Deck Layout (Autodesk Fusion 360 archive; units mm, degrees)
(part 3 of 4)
sketch "Right Launch Alley Wall" plane through (0, 0, 0) normal (0, 0, 1) x axis (1, 0, 0)
  line L1 (465, 200) -> (0.189, 200)
  line L2 (465, 200) -> (475.0152, 200)
  line L3 (465, 400) -> (465, 200.5)
  line L4 (475.0152, 200.5) -> (475.0152, 405.3897)
  line L5 (475.0152, 200.5) -> (465, 200.5)
  line L6 (465, 535) -> (465, 427.4801)
  line L7 (448.6603, 535) -> (465, 535)
  line L8 (465.6699, 579.4615) -> (444.3301, 542.5)
  line L9 (475, 576.9615) -> (475, 423.4891)
  circle C1 centre (470.0076, 235) radius 2.25
  circle C2 centre (470.0076, 235) radius 4
  circle C3 centre (470.0076, 350) radius 4
  circle C4 centre (470.0076, 350) radius 2.25
  circle C5 centre (465, 412) radius 2.25
  arc A1 centre (465, 412) radius 12 clockwise from (475.0152, 405.3897) to (465, 400)
  circle C6 centre (465, 412) radius 9
  arc A2 centre (465, 412) radius 12 clockwise from (468, 423.619) to (471.8571, 421.8478)
  circle C7 centre (470, 435) radius 4
  circle C8 centre (470, 435) radius 1.9
  circle C9 centre (470, 574) radius 1.9
  circle C10 centre (470, 574) radius 4
  circle C11 centre (470, 505) radius 1.9
  circle C12 centre (470, 505) radius 4
  circle C13 centre (450, 541) radius 1.9
  circle C14 centre (450, 541) radius 4
  arc A3 centre (448.6603, 540) radius 5 clockwise from (448.6603, 535) to (444.3301, 542.5)
  arc A4 centre (470, 576.9615) radius 5 clockwise from (465.6699, 579.4615) to (475, 576.9615)
  arc A5 centre (469, 427.4919) radius 4 clockwise from (468, 423.619) to (465, 427.4919)
  arc A6 centre (473, 423.4891) radius 2 clockwise from (475, 423.4891) to (471.8571, 421.8478)
  point P2 (475.0152, 200)
  point P6 (475.0152, 200)
  point P3 (465, 200)
  point P7 (465, 200)
  point P13 (465, 412)
  point P14 (465, 412)
  point P21 (465, 412)
  point P39 (465, 427.4801)
  coincident P2 P6
  coincident P3 P7
  perpendicular L1 L3
  perpendicular L2 L4
  concentric C1 C2
  concentric C3 C4
  coincident P13 P14
  concentric A1 C6
  perpendicular L4 L5
  vertical L6
  perpendicular L6 L7
  vertical L9
  coincident P14 P21
  concentric C7 C8
  concentric C9 C10
  concentric C11 C12
  concentric C13 C14
  tangent L7 A3
  tangent L8 A3
  tangent L8 A4
  tangent L9 A4
  tangent A2 A5
  coincident A5 P39
  tangent A2 A6
  tangent L9 A6
  dimension "d456" diameter C1 = 4.5
  dimension "d457" diameter C2 = 8
  dimension "d458" diameter C4 = 4.5
  dimension "d459" diameter C3 = 8
  dimension "d461" diameter C5 = 4.5
  dimension "d469" diameter C6 = 18
  dimension "d481" radius A2 = 12
  dimension "d484" radius A3 = 5
  dimension "d485" radius A4 = 5
  dimension "d486" radius A5 = 4
  dimension "d487" radius A6 = 2
extrude "Extrude76" new body sketch "Right Launch Alley Wall" profile of L2 L3 L4 C2 C3 A1 along normal blind 25 bodies "Right Launch Runway"
extrude "Extrude77" add sketch "Right Launch Alley Wall" profile of C1 C2 C3 C4 along normal blind 4
fillet "Fillet24" radius 1
fillet "Fillet25" radius 2
extrude "Extrude78" new body sketch "Right Launch Alley Wall" profile of L6 L7 L8 L9 A2 C7 C10 C12 C14 A3 A4 A5 A6 along normal blind 25 bodies "Right Launch Runway Top"
extrude "Extrude79" add sketch "Right Launch Alley Wall" profile of C7 C8 C9 C10 C11 C12 C13 C14 along normal blind 4
fillet "Fillet26" radius 0.8
extrude "Extrude80" new body sketch "Bottom Runways" along normal blind 25 bodies "Left Middle Runway"
extrude "Extrude81" add sketch "Bottom Runways" along normal blind 4
fillet "Fillet27" radius 1.4
extrude "Extrude82" new body sketch "Bottom Runways" along normal blind 25 bodies "Left Upper Runway"
extrude "Extrude83" add sketch "Bottom Runways" along normal blind 4
fillet "Fillet29" radius 2
fillet "Fillet30" radius 4
fillet "Fillet31" radius 2
fillet "Fillet32" radius 2
combine "Combine5"
fillet "Fillet33" radius 2
extrude "Extrude84" new body sketch "Top Runways" profile of L19 L20 L21 L22 K1 C33 C36 C37 along normal blind 25 bodies "Top Left Curve"
extrude "Extrude85" add sketch "Top Runways" profile of C33 C34 C35 C36 C37 C38 along normal blind 4
fillet "Fillet34" radius 2
fillet "Fillet35" radius 2
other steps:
derived_base_feature "Derived Base Feature" bodies "Flipper_Straight"
base_feature "Base Feature" bodies "Flipper_Straight (1)"
named bodies: "Flipper_Straight", "Flipper_Straight (1)", "Left Loweer Deck Section", "Middle Lower Deck Section", "Right Lower Deck Section", "Z Reload Plunger", "Reload Ball Release Lower Washer", "Reload Ball Release Drive", "Reload Ball Release Solenoid Coupling", "Reload Ball Release Slide", "Reload Ball Release Slide Coupling", "Left Loweer Deck Section (1)", "Reload Solenoid", "Reload Load Coupling Bushing", "Reload Load Flipper", "Reload Load Coupling", "Reload Load Retaining Washer", "Reload Ball Release Slide (1)", "Reload Ball Release Washer", "Top Right Corner", "Outer Runway Right", "Outer Runway Left", "Right Launch Runway", "Right Launch Runway Top", "Left Middle Runway", "Left Upper Runway", "Top Left Curve"

design "Pinball Flipper Full bushing"
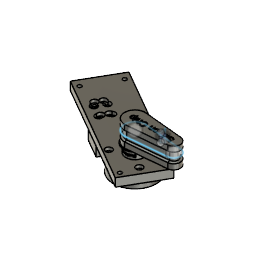
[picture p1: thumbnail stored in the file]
sketch "Flipper" plane through (0, 0, 0) normal (0, 0, 1) x axis (1, 0, 0)
  line L1 (47.7564, -7.9642) -> (0, -12.5)
  line L2 (47.766, 7.9632) -> (1.1968, 12.4426)
  line L3 (-3.0757, 6.1628) -> (6.875, 0.4178)
  line L4 (-6.875, -0.4178) -> (3.0757, -6.1628)
  arc A1 centre (0, 0) radius 12.5 clockwise from (2.3532, -12.2765) to (1.1968, 12.4426)
  arc A2 centre (47, 0) radius 8 clockwise from (47.766, 7.9632) to (47.7564, -7.9642)
  circle C1 centre (0, 0) radius 6.8
  circle C2 centre (3.7239, -2.15) radius 1.4
  circle C3 centre (-3.7239, 2.15) radius 1.4
  point P1 (0, 0)
  point P2 (0, 0)
  point P4 (0, -12.5)
  point P8 (2.3532, -12.2765)
  point P9 (0, 0)
  point P3 (47, 0)
  coincident P1 P2
  coincident P4 A1
  tangent L1 A2
  tangent L2 A1
  tangent L2 A2
  coincident L1 P8
  coincident P1 P9
  dimension "d6" diameter C1 = 13.6
  dimension "d87" angle P3 = 150
  dimension "d174" diameter P3 = 4
  dimension "d363" diameter C2 = 2.8
  dimension "d364" diameter C3 = 2.8
sketch "Bushing" plane through (0, 0, 0) normal (0, 0, 1) x axis (1, 0, 0)
  circle C1 centre (0, 0) radius 7.3
  circle C2 centre (0, 0) radius 11
  point P1 (0, 0)
  point P2 (0, 0)
  point P3 (0, 0)
  coincident P1 P2
  coincident P1 P3
extrude "Extrude1" new body sketch "Flipper" blind 25 from offset 0.7 bodies "DO NOT USE FLIPPER PROTO"
extrude "Extrude2" add sketch "Flipper" profile of C1 L4 L3 C2 C3 against normal blind 30.8 and along normal blind 0.7
sketch "Washers Upper" plane through (0, 0, 0) normal (0, 0, 1) x axis (1, 0, 0)
  circle C1 centre (0, 0) radius 13.5
  circle C2 centre (0, 0) radius 7.3
  point P1 (0, 0)
  point P2 (0, 0)
  point P3 (0, 0)
  coincident P1 P2
  coincident P1 P3
  dimension "d368" diameter C1 = 27
extrude "Extrude3" new body sketch "Washers Upper" blind -0.8 from offset 0.4 bodies "Washer Upper"
extrude "Extrude4" new body sketch "Bushing" blind -29 from offset -10.2 bodies "Base and Bushing"
sketch "Deck Section" plane through (0, 0, 0) normal (0, 0, 1) x axis (1, 0, 0)
  line L1 (-50, 50) -> (-50, 0)
  line L2 (50, 50) -> (-50, 50)
  line L3 (50, -50) -> (50, 50)
  line L4 (-50, -50) -> (50, -50)
  line L5 (-50, 0) -> (-50, -50)
  circle C1 centre (0, 0) radius 11.5
  point P1 (0, 0)
  point P2 (0, 0)
  coincident P1 P2
  vertical L1
  perpendicular L1 L2
  perpendicular L2 L3
  perpendicular L3 L4
  perpendicular L2 L5
extrude "Extrude5" new body sketch "Deck Section" blind -9 from offset -1.2 bodies "Base Section"
sketch "Solenoid Assembly" plane through (0, 0, -10.2) normal (0, 0, -1) x axis (1, 0, 0)
  line L1 (25, -25) -> (25, 25)
  line L2 (-100, -25) -> (25, -25)
  line L3 (-100, 25) -> (-100, -25)
  line L4 (25, 25) -> (-100, 25)
  circle C1 centre (0, 0) radius 11.5
  circle C2 centre (0, 0) radius 7.3
  point P1 (0, 0)
  point P3 (0, 0)
  coincident P1 P3
  vertical L1
  perpendicular L2 L3
  perpendicular L1 L4
sketch "Solenoid 22mm" plane through (0, 0, 0) normal (0, 0, 1) x axis (1, 0, 0)
  line L1 (-11, 0) -> (-11, -26)
  line L2 (11, -26) -> (11, 0)
  line L3 (-11, -26) -> (11, -26)
  line L4 (11, 0) -> (-11, 0)
  circle C1 centre (6, -5) radius 1.8
  circle C2 centre (-6, -20.5) radius 1.8
  point P2 (11, -26)
  point P3 (11, -26)
  point P4 (11, -26)
  coincident P2 P3
  horizontal L3
  perpendicular L1 L3
  perpendicular L1 L4
  coincident P2 P4
  perpendicular L2 L3
sketch "Solenoid 37mm" plane through (0, 0, 0) normal (0, 0, 1) x axis (1, 0, 0)
  line L1 (-2.5, -5.5015) -> (-2.506, -11.3658)
  line L2 (-11, 0) -> (-11, -37)
  line L3 (-5.5, -5.5015) -> (-5.494, -11.3656)
  line L4 (-11, 0) -> (11, 0)
  line L5 (2.5, -31.4995) -> (2.5022, -25.4191)
  line L6 (-2.5, -25.5008) -> (-2.503, -31.4046)
  line L7 (5.5, -25.5) -> (5.5, -31.5)
  line L8 (11, 0) -> (11, -37)
  line L9 (-5.5, -25.5) -> (-5.5, -31.5)
  line L10 (-11, -37) -> (11, -37)
  line L11 (2.5, -5.5015) -> (2.506, -11.3658)
  line L12 (-11, 0) -> (-11, -37)
  line L13 (-11, 0) -> (11, 0)
  line L14 (11, 0) -> (11, -37)
  line L15 (5.5, -5.5015) -> (5.494, -11.3656)
  line L16 (-11, -37) -> (11, -37)
  line L17 (-11, 0) -> (-11, -37)
  line L18 (-11, 0) -> (11, 0)
  line L19 (2.5, -31.4995) -> (2.5021, -25.5799)
  line L20 (5.5, -25.5) -> (5.5, -31.5)
  line L21 (11, 0) -> (11, -37)
  line L22 (-11, -37) -> (11, -37)
  circle C1 centre (4, -28.5) radius 1.5
  arc A1 centre (-4, -31.5) radius 1.5 clockwise from (-2.503, -31.4046) to (-5.5, -31.5)
  arc A2 centre (-4, -25.5) radius 1.5 clockwise from (-5.5, -25.5) to (-2.5, -25.5008)
  arc A3 centre (-4, -11.5) radius 1.5 clockwise from (-2.506, -11.3658) to (-5.494, -11.3656)
  arc A4 centre (4, -11.5) radius 1.5 clockwise from (5.4939, -11.365) to (2.5061, -11.365)
  circle C2 centre (-4, -28.5) radius 1.5
  arc A5 centre (4, -31.5) radius 1.5 clockwise from (5.5, -31.5) to (2.5, -31.4995)
  arc A6 centre (4, -25.5) radius 1.5 clockwise from (2.5022, -25.4191) to (5.5, -25.5)
  arc A7 centre (-4, -5.5) radius 1.5 clockwise from (-5.5, -5.5015) to (-2.5, -5.5015)
  circle C3 centre (-4, -8.5) radius 1.5
  circle C4 centre (4, -8.5) radius 1.5
  circle C5 centre (4, -28.5) radius 1.5
  arc A8 centre (-4, -31.5) radius 1.5 clockwise from (-2.503, -31.4045) to (-5.5, -31.5)
  arc A9 centre (4, -5.5) radius 1.5 clockwise from (2.5, -5.5015) to (5.5, -5.5015)
  arc A10 centre (-4, -11.5) radius 1.5 clockwise from (-2.5061, -11.365) to (-5.4939, -11.365)
  arc A11 centre (4, -11.5) radius 1.5 clockwise from (5.494, -11.3656) to (2.506, -11.3658)
  circle C6 centre (-4, -28.5) radius 1.5
  arc A12 centre (4, -31.5) radius 1.5 clockwise from (5.5, -31.5) to (2.5, -31.4995)
  circle C7 centre (-4, -8.5) radius 1.5
  circle C8 centre (4, -8.5) radius 1.5
  circle C9 centre (4, -28.5) radius 1.5
  arc A13 centre (-4, -31.5) radius 1.5 clockwise from (-2.503, -31.4045) to (-5.5, -31.5)
  arc A14 centre (-4, -11.5) radius 1.5 clockwise from (-2.5061, -11.365) to (-5.4939, -11.365)
  arc A15 centre (4, -11.5) radius 1.5 clockwise from (5.4939, -11.365) to (2.5061, -11.365)
  circle C10 centre (-4, -28.5) radius 1.5
  arc A16 centre (4, -31.5) radius 1.5 clockwise from (5.5, -31.5) to (2.5, -31.4995)
  arc A17 centre (4, -25.5) radius 1.5 clockwise from (2.5021, -25.5799) to (5.5, -25.5)
  circle C11 centre (-4, -8.5) radius 1.5
  circle C12 centre (4, -8.5) radius 1.5
  point P28 (2.5, -31.4995)
  point P7 (2.5, -31.4995)
  point P83 (2.5, -31.4995)
  point P67 (2.5, -31.4995)
  tangent L1 A7
  tangent L3 A7
  tangent A2 L6
  tangent A6 L7
  coincident P28 A5
  tangent A5 L5
  tangent A2 L9
  coincident P7 L5
  tangent A9 L15
  tangent L11 A9
  tangent A17 L20
  coincident P83 A16
  tangent A16 L19
  coincident P67 L19
extrude "Extrude6" new body sketch "Solenoid 22mm" along normal blind 25 bodies "Solenoid 22mm"
extrude "Extrude7" new body sketch "Solenoid 37mm" along normal blind 26 bodies "Solenoid 37mm"
sketch "Solenoid 37mm Plunger" plane through (0, -37, 0) normal (0, -1, 0) x axis (1, 0, 0)
  line L1 (11, 0) -> (-11, 0)
  line L2 (11, 26) -> (11, 0)
  line L3 (-11, 26) -> (11, 26)
  line L4 (-11, 0) -> (-11, 26)
  circle C1 centre (0, 12.5) radius 4
extrude "Extrude8" add sketch "Solenoid 37mm Plunger" profile of C1 along normal blind 23
sketch "Solenoid 22mm Plunger" plane through (0, -26, 0) normal (0, -1, 0) x axis (1, 0, 0)
  line L1 (11, 0) -> (-11, 0)
  line L2 (11, 25) -> (11, 0)
  line L3 (-11, 25) -> (11, 25)
  line L4 (-11, 0) -> (-11, 25)
  circle C1 centre (0, 12.5) radius 4
extrude "Extrude9" add sketch "Solenoid 22mm Plunger" profile of C1 along normal blind 20
sketch "Washer Lower TBA" plane through (0, 0, -10.2) normal (0, 0, -1) x axis (1, 0, 0)
  circle C1 centre (0, 0) radius 15
  circle C2 centre (0, 0) radius 11.5
  dimension "d38" diameter C1 = 30
move_face "MoveFace1"
extrude "Extrude11" cut sketch "Flipper" profile of C1 L4 L3 blind -19 taper 3 from offset -22.3
sketch "Flipper Drive" plane through (0, 0, -10.2) normal (0, 0, -1) x axis (1, 0, 0)
  line L1 (2.8887, 6.4858) -> (-7.0612, 0.7412)
  line L2 (7.0612, -0.7412) -> (-2.8887, -6.4858)
  line L3 (-7.5, 12.9904) -> (0, 0)
  line L4 (2.0367, 12.7229) -> (-5, 8.6603)
  line L5 (19.5843, 19.5843) -> (0, 0)
  line L6 (28.1764, 0) -> (0, 0)
  line L7 (-23.0757, -23.0757) -> (0, 0)
  line L8 (33.1997, 0) -> (0, 0)
  line L9 (5.1764, 19.3185) -> (0, 0)
  line L10 (26.3861, 0) -> (0, 0)
  line L11 (-5.1764, 19.3185) -> (0, 0)
  line L12 (28.3599, 0) -> (0, 0)
  line L13 (0, 0) -> (-5.1764, -19.3185)
  line L14 (0, 0) -> (5.1764, -19.3185)
  line L15 (19.1868, -19.1868) -> (0, 0)
  line L16 (27.1343, 0) -> (0, 0)
  line L17 (0, 0) -> (-19.1868, 19.1868)
  line L18 (23.3932, -6.2682) -> (0, 0)
  line L19 (24.2184, 0) -> (0, 0)
  line L20 (0, 0) -> (-22.295, 10.3963)
  line L21 (24.2161, 6.4887) -> (0, 0)
  line L22 (23.6444, 0) -> (0, 0)
  line L23 (0, 0) -> (-21.6626, -10.1014)
  line L24 (-28.4442, -13.2638) -> (0, 0)
  line L25 (31.3847, 0) -> (0, 0)
  line L26 (-25.8113, 12.036) -> (0, 0)
  line L27 (28.4796, 0) -> (0, 0)
  line L28 (29.5346, -7.9138) -> (23.3932, -6.2682)
  line L29 (31.5373, 8.4504) -> (24.2161, 6.4887)
  arc A1 centre (0, 0) radius 7.1 clockwise from (-2.8887, -6.4858) to (-7.0612, 0.7412)
  arc A2 centre (0, 0) radius 7.1 clockwise from (2.8887, 6.4858) to (7.0612, -0.7412)
  circle C1 centre (0, 0) radius 15
  arc A3 centre (0, 0) radius 7.1 clockwise from (-7.0612, 0.7412) to (2.8887, 6.4858)
  arc A4 centre (0, 0) radius 7.1 clockwise from (7.0612, -0.7412) to (-2.8887, -6.4858)
  arc A5 centre (0, 0) radius 20 clockwise from (-5.1764, 19.3185) to (5.1764, 19.3185)
  arc A6 centre (0, 0) radius 20 clockwise from (5.1764, -19.3185) to (-5.1764, -19.3185)
  arc A7 centre (0, 0) radius 16 clockwise from (11.3137, 11.3137) to (15.4548, 4.1411)
  arc A8 centre (0, 0) radius 16 clockwise from (15.4548, -4.1411) to (11.3137, -11.3137)
  arc A9 centre (0, 0) radius 16 clockwise from (-11.3137, -11.3137) to (-14.5009, -6.7619)
  arc A10 centre (0, 0) radius 16 clockwise from (-14.5009, 6.7619) to (-11.3137, 11.3137)
  arc A11 centre (0, 0) radius 16 clockwise from (15.4548, 4.1411) to (15.4548, -4.1411)
  arc A12 centre (0, 0) radius 16 clockwise from (-14.5009, -6.7619) to (-14.5009, 6.7619)
  arc A13 centre (0, 0) radius 21 clockwise from (-19.0325, -8.875) to (-19.0325, 8.875)
  arc A14 centre (0, 0) radius 26 clockwise from (18.3848, 18.3848) to (18.3848, -18.3848)
  arc A15 centre (0, 0) radius 26 clockwise from (-18.3848, -18.3848) to (-23.564, -10.9881)
  arc A16 centre (0, 0) radius 26 clockwise from (-23.564, 10.9881) to (-18.3848, 18.3848)
  arc A17 centre (0, 0) radius 26 clockwise from (18.3848, -18.3848) to (-18.3848, -18.3848)
  arc A18 centre (0, 0) radius 21 clockwise from (-14.8492, 14.8492) to (14.8492, 14.8492)
  arc A19 centre (0, 0) radius 26 clockwise from (-18.3848, 18.3848) to (18.3848, 18.3848)
  arc A20 centre (0, 0) radius 21 clockwise from (14.8492, -14.8492) to (-14.8492, -14.8492)
  circle C2 centre (-18.564, -12.9881) radius 1.75
  circle C3 centre (-18.564, -12.9881) radius 4
  circle C4 centre (-18.564, 13.0119) radius 1.75
  circle C5 centre (-18.564, 13.0119) radius 4
  circle C6 centre (18.436, 13.0119) radius 1.75
  circle C7 centre (18.436, 13.0119) radius 4
  circle C8 centre (18.436, -12.9881) radius 1.75
  circle C9 centre (18.436, -12.9881) radius 4
  arc A21 centre (0, 0) radius 26 clockwise from (-23.564, -10.9881) to (-23.564, 10.9881)
  point P1 (0, 0)
  point P2 (0, 0)
  point P3 (7.0612, -0.7412)
  point P8 (0, 0)
  point P12 (-7.5, 12.9904)
  point P7 (0, 0)
  point P15 (0, 0)
  point P14 (0, 0)
  point P18 (0, 0)
  point P11 (0, 0)
  point P21 (0, 0)
  point P23 (0, 0)
  point P26 (0, 0)
  point P27 (0, 0)
  point P30 (0, 0)
  point P33 (0, 0)
  point P38 (0, 0)
  point P43 (0, 0)
  point P49 (15.4548, 4.1411)
  point P50 (11.3137, 11.3137)
  point P48 (0, 0)
  point P53 (15.4548, -4.1411)
  point P36 (0, 0)
  point P51 (0, 0)
  point P55 (-14.5009, -6.7619)
  point P54 (0, 0)
  point P57 (-19.0325, -8.875)
  point P58 (-19.0325, 8.875)
  point P61 (-14.5009, 6.7619)
  point P60 (-11.3137, 11.3137)
  point P59 (0, 0)
  point P62 (0, 0)
  point P46 (-21.6626, -10.1014)
  point P65 (0, 0)
  point P41 (-22.295, 10.3963)
  point P68 (0, 0)
  point P13 (0, 0)
  point P71 (0, 0)
  point P75 (18.3848, 18.3848)
  point P77 (-23.564, -10.9881)
  point P76 (0, 0)
  point P81 (-23.564, 10.9881)
  point P79 (0, 0)
  point P82 (0, 0)
  point P85 (-14.8492, 14.8492)
  point P83 (0, 0)
  point P86 (0, 0)
  point P88 (-14.8492, -14.8492)
  point P73 (0, 0)
  point P87 (0, 0)
  point P42 (0, 0)
  point P98 (0, 0)
  coincident P1 P2
  coincident P3 A1
  coincident P2 P8
  concentric A1 C1
  coincident C1 P12
  horizontal L6
  coincident P7 P15
  horizontal L8
  coincident P14 P18
  horizontal L10
  coincident P11 P21
  horizontal L12
  coincident P2 P23
  coincident P26 P27
  coincident P27 P30
  horizontal L16
  coincident P7 P33
  horizontal L19
  coincident P11 P38
  horizontal L22
  coincident P2 P43
  coincident L21 P49
  coincident L5 P50
  coincident P14 P48
  coincident L18 P53
  coincident P36 P51
  coincident L23 P55
  coincident P1 P54
  coincident L23 P57
  coincident L20 P58
  coincident L20 P61
  coincident L17 P60
  coincident P27 P59
  horizontal L25
  coincident P1 P62
  coincident P46 L24
  parallel L23 L24
  horizontal L27
  coincident P7 P65
  coincident P41 L26
  parallel L20 L26
  coincident P51 P68
  parallel L18 L28
  parallel L21 L29
  coincident P13 P71
  coincident L5 P75
  coincident L24 P77
  coincident P13 P76
  coincident L26 P81
  coincident P54 P79
  coincident P54 P82
  coincident L17 P85
  coincident P82 P83
  coincident P59 P86
  coincident L7 P88
  coincident P73 P87
  concentric C2 C3
  concentric C4 C5
  concentric C8 C9
  concentric C6 C7
  coincident P42 P98
  dimension "d299" angle L7 L8 = 135
  dimension "d300" angle L9 L10 = 75
  dimension "d301" angle L11 L12 = 105
  dimension "d302" radius A5 = 20
  dimension "d303" radius A6 = 20
  dimension "d307" radius A7 = 16
  dimension "d309" radius A8 = 16
  dimension "d311" radius A9 = 16
  dimension "d314" radius A10 = 16
  dimension "d513" radius A14 = 26
  dimension "d514" radius A15 = 26
  dimension "d515" radius A16 = 26
  dimension "d517" radius A18 = 21
  dimension "d518" radius A20 = 21
  dimension "d520" diameter C2 = 3.5
  dimension "d521" diameter C3 = 8
  dimension "d522" diameter C4 = 3.5
  dimension "d523" diameter C5 = 8
  dimension "d524" diameter C8 = 3.5
  dimension "d525" diameter C9 = 8
  dimension "d526" diameter C6 = 3.5
  dimension "d527" diameter C7 = 8
work_plane "WorkPlane1" RotateAngle 90
sketch "Flipper Drive Perpendicular Plane" plane through (0, 0, 0) normal (-0.866, 0.5, 0) x axis (-0.5, -0.866, 0)
  circle C1 centre (10, -32.2) radius 2
  circle C2 centre (10, -32.2) radius 4.5
  circle C3 centre (-10, -32.2) radius 2
  circle C4 centre (-10, -32.2) radius 4.5
  dimension "d51" diameter C1 = 4
  dimension "d52" diameter C2 = 9
  dimension "d53" diameter C3 = 4
  dimension "d54" diameter C4 = 9
extrude "Extrude12" new body sketch "Flipper Drive" profile of A2 C1 A3 A4 blind 8.8 from offset 11.2 bodies "Flipper Drive"
extrude "Extrude13" add sketch "Flipper Drive" profile of L1 L2 L3 A3 A4 blind 8.8 taper 3 from offset 11.2
sketch "Flipper Drive Top Labelling" plane through (0, 0, -30.2) normal (0, 0, -1) x axis (1, 0, 0)
  line L1 (3.3862, 6.2405) -> (-7.0975, 0.1877)
  line L2 (-3.3862, -6.2405) -> (7.0975, -0.1877)
  curve K1
  curve K2
  curve K3
  curve K4
  curve K5
  curve K6
  curve K7
  curve K8
  line L3 (10, 0) -> (0, 0)
  line L4 (3.3862, 6.2405) -> (-7.0975, 0.1877)
  line L5 (-3.3862, -6.2405) -> (7.0975, -0.1877)
  arc A1 centre (0, 0) radius 7.1 clockwise from (-3.3862, -6.2405) to (-7.0975, 0.1877)
  circle C1 centre (-5, 8.6603) radius 5
  circle C2 centre (-5, 8.6603) radius 3
  circle C3 centre (-5, 8.6603) radius 1.4
  arc A2 centre (0, 0) radius 7.1 clockwise from (3.3862, 6.2405) to (7.0975, -0.1877)
  circle C4 centre (0, 0) radius 15
  arc A3 centre (0, 0) radius 7.1 clockwise from (-3.3862, -6.2405) to (-7.0975, 0.1877)
  arc A4 centre (0, 0) radius 7.1 clockwise from (3.3862, 6.2405) to (7.0975, -0.1877)
  circle C5 centre (0, 0) radius 15
  point P1 (0, 0)
  point P8 (0, 0)
  horizontal L3
  coincident P1 P8
  concentric C1 C2
  concentric C1 C3
  dimension "d512" diameter C3 = 2.8
  dimension "d75" Text1-Height = 5
  dimension "d77" Text2-Height = 3
extrude "Extrude20" cut sketch "Flipper Drive Top Labelling" against normal blind 0.6
sketch "Flipper Drive Lower Assembly" plane through (0, 0, -10.2) normal (0, 0, -1) x axis (1, 0, 0)
  line L1 (40.6874, -6.549) -> (14.7287, 38.4892)
  line L2 (-113.7703, -35.5739) -> (14.7287, 38.4892)
  line L3 (-87.8117, -80.6121) -> (12.9793, -22.5191)
  line L4 (40.6874, -6.549) -> (12.9793, -22.5191)
  line L5 (-87.8117, -80.6121) -> (-113.7703, -35.5739)
  line L6 (20.7934, 41.9847) -> (14.7287, 38.4892)
  line L7 (46.7521, -3.0534) -> (40.6874, -6.549)
  line L8 (-94.1551, -30.9647) -> (-102.8153, -35.9647)
  line L9 (-83.4756, -35.9647) -> (-102.8153, -35.9647)
  line L10 (-90.691, -28.9647) -> (-94.1551, -30.9647)
  line L11 (19.0606, 40.986) -> (14.7287, 38.4892)
  circle C1 centre (0, 0) radius 11
  circle C2 centre (-82.8153, -70.6057) radius 2.25
  circle C3 centre (-102.8153, -35.9647) radius 2.25
  circle C4 centre (12.3745, 30.5207) radius 2.25
  circle C5 centre (32.3745, -4.1204) radius 2.25
  point P1 (0, 0)
  point P2 (0, 0)
  point P9 (-102.8153, -35.9647)
  point P14 (-102.8153, -35.9647)
  point P15 (-94.1551, -30.9647)
  point P17 (-90.691, -28.9647)
  point P3 (14.7287, 38.4892)
  point P18 (19.0606, 40.986)
  coincident P1 P2
  perpendicular L1 L2
  perpendicular L1 L4
  perpendicular L3 L5
  perpendicular L1 L6
  perpendicular L1 L7
  horizontal L9
  coincident P9 P14
  parallel L8 L10
  perpendicular L1 L11
  dimension "d132" diameter C2 = 4.5
  dimension "d135" diameter C3 = 4.5
  dimension "d138" diameter C4 = 4.5
  dimension "d139" diameter C5 = 4.5
  dimension "d348" angle L8 L9 = 30
  dimension "d349" distance P14 P15 = 10
  dimension "d357" distance P15 P17 = 4
  dimension "d534" distance P3 P18 = 5
extrude "Extrude21" add sketch "Flipper Drive Lower Assembly" profile of C1 L1 L2 L3 L4 L5 along normal blind 10
sketch "Washer Lower" plane through (0, 0, -20.2) normal (0, 0, -1) x axis (1, 0, 0)
  circle C1 centre (0, 0) radius 7.3
  circle C2 centre (0, 0) radius 7.3
  circle C3 centre (0, 0) radius 13.5
  point P1 (0, 0)
  point P3 (0, 0)
  coincident P1 P3
  dimension "d369" diameter C3 = 27
extrude "Extrude22" new body sketch "Washer Lower" blind 1 from offset 0.2 bodies "Washer Lower"
move "Move1"
move "Move2"
move "Move3"
move "Move4"
work_plane "WorkPlane2" RotateAngle 0
sketch "Construction to Solenoid" plane through (0, 0, -32.2) normal (0, 0, 1) x axis (1, 0, 0)
  line L1 (-83.5481, 36.6895) -> (-5, -8.6603)
  line L2 (85.6995, -8.6603) -> (-5, -8.6603)
  point P2 (-5, -8.6603)
  point P3 (-5, -8.6603)
  horizontal L2
  coincident P2 P3
  dimension "d87" angle L1 L2 = 150
move "Move5"
work_axis "WorkAxis2"
move "Move6"
move "Move7"
work_plane "WorkPlane3" AlongDistance 12.5
work_plane "WorkPlane4" RotateAngle 0
work_plane "WorkPlane5" RotateAngle 0
sketch "Solenoid Coupling" plane through (0, 0, -32.2) normal (0, 0, 1) x axis (1, 0, 0)
  line L1 (14.8548, -15.2705) -> (9.7533, -24.1063)
  line L2 (30.5284, -24.3335) -> (14.8548, -15.2705)
  line L3 (25.433, -33.159) -> (30.5284, -24.3335)
  line L4 (25.433, -33.159) -> (9.7533, -24.1063)
  line L5 (47.3229, -34.0286) -> (34.864, -26.8366)
  line L6 (30.5284, -24.3335) -> (34.864, -26.8366)
  line L7 (34.864, -26.8366) -> (30.629, -34.173)
  line L8 (13.6506, -26.3564) -> (16.6506, -21.1603)
  line L9 (22.6506, -21.1603) -> (16.6506, -21.1603)
  line L10 (13.6506, -26.3564) -> (16.6506, -21.1603)
  line L11 (51.0602, -47.9614) -> (53.55, -46.5429)
  line L12 (51.0602, -47.9614) -> (42.896, -43.2346)
  line L13 (-25.136, -26.8366) -> (-29.3244, -34.0923)
  line L14 (-45.1452, -15.2705) -> (-50.2467, -24.1063)
  line L15 (-34.567, -33.159) -> (-29.4716, -24.3335)
  line L16 (-46.3494, -26.3564) -> (-43.3494, -21.1603)
  line L17 (-8.2143, -48.5931) -> (-5.4963, -46.9921)
  line L18 (-11.811, -34.5286) -> (-25.136, -26.8366)
  line L19 (-29.4716, -24.3335) -> (-25.136, -26.8366)
  line L20 (-29.4716, -24.3335) -> (-45.1452, -15.2705)
  line L21 (-37.3494, -21.1603) -> (-43.3494, -21.1603)
  line L22 (-46.3494, -26.3564) -> (-43.3494, -21.1603)
  line L23 (-10.945, -35.0285) -> (-11.811, -34.5286)
  line L24 (-15.3719, -42.1478) -> (-16.2379, -41.6478)
  line L25 (-89.4716, -24.3335) -> (-105.1452, -15.2705)
  line L26 (-97.3494, -21.1603) -> (-103.3494, -21.1603)
  line L27 (-67.4648, -48.7967) -> (-64.8096, -47.2494)
  line L28 (-106.3494, -26.3564) -> (-103.3494, -21.1603)
  line L29 (-106.3494, -26.3564) -> (-103.3494, -21.1603)
  line L30 (-69.7504, -35.7181) -> (-70.6165, -35.2181)
  line L31 (-70.6165, -35.2181) -> (-85.136, -26.8366)
  line L32 (-74.5059, -42.6477) -> (-75.3719, -42.1477)
  line L33 (-85.136, -26.8366) -> (-89.3244, -34.0922)
  line L34 (-67.4648, -48.7967) -> (-75.3719, -44.2345)
  line L35 (-89.4716, -24.3335) -> (-85.136, -26.8366)
  line L36 (-94.567, -33.159) -> (-89.4716, -24.3335)
  line L37 (-105.1452, -15.2705) -> (-110.2467, -24.1063)
  line L38 (-94.567, -33.159) -> (-110.2467, -24.1063)
  line L39 (-156.3494, -26.3564) -> (-153.3494, -21.1603)
  line L40 (-155.1452, -15.2705) -> (-160.2467, -24.1063)
  line L41 (-147.3494, -21.1603) -> (-153.3494, -21.1603)
  line L42 (-119.2129, -36.0285) -> (-120.0789, -35.5285)
  line L43 (-116.307, -49.4732) -> (-113.7939, -48.0094)
  line L44 (-156.3494, -26.3564) -> (-153.3494, -21.1603)
  line L45 (-144.567, -33.159) -> (-139.4716, -24.3335)
  line L46 (-134.27, -27.3366) -> (-138.4584, -34.5922)
  line L47 (-144.567, -33.159) -> (-160.2467, -24.1063)
  line L48 (-139.4716, -24.3335) -> (-134.27, -27.3366)
  line L49 (-139.4716, -24.3335) -> (-155.1452, -15.2705)
  line L50 (-120.0789, -35.5285) -> (-134.27, -27.3366)
  line L51 (-123.6398, -43.1477) -> (-124.5059, -42.6477)
  line L52 (-116.307, -49.4732) -> (-124.5058, -44.7345)
  line L53 (-204.567, -33.159) -> (-220.2467, -24.1063)
  line L54 (-182.7738, -43.6477) -> (-183.6398, -43.1477)
  line L55 (-207.3494, -21.1603) -> (-213.3494, -21.1603)
  line L56 (-215.1452, -15.2705) -> (-220.2467, -24.1063)
  line L57 (-216.3494, -26.3564) -> (-213.3494, -21.1603)
  line L58 (-216.3494, -26.3564) -> (-213.3494, -21.1603)
  line L59 (-199.4716, -24.3335) -> (-215.1452, -15.2705)
  line L60 (-199.4716, -24.3335) -> (-193.404, -27.8366)
  line L61 (-178.3469, -36.5285) -> (-179.2129, -36.0285)
  line L62 (-179.2129, -36.0285) -> (-193.404, -27.8366)
  line L63 (-175.4401, -49.9688) -> (-183.6398, -45.2345)
  line L64 (-204.567, -33.159) -> (-199.4716, -24.3335)
  line L65 (-175.4401, -49.9688) -> (-172.9348, -48.5134)
  line L66 (-193.404, -27.8366) -> (-197.5924, -35.0922)
  line L67 (-264.567, -33.159) -> (-280.2467, -24.1063)
  line L68 (-275.1452, -15.2705) -> (-280.2467, -24.1063)
  line L69 (-234.5746, -50.467) -> (-232.0726, -49.0156)
  line L70 (-238.3469, -36.5285) -> (-252.538, -28.3366)
  line L71 (-259.4716, -24.3335) -> (-252.538, -28.3366)
  line L72 (-252.538, -28.3366) -> (-256.7263, -35.5922)
  line L73 (-234.5746, -50.467) -> (-242.7738, -45.7345)
  line L74 (-259.4716, -24.3335) -> (-275.1452, -15.2705)
  line L75 (-267.3494, -21.1603) -> (-273.3494, -21.1603)
  line L76 (-276.3494, -26.3564) -> (-273.3494, -21.1603)
  line L77 (-276.3494, -26.3564) -> (-273.3494, -21.1603)
  line L78 (-264.567, -33.159) -> (-259.4716, -24.3335)
  line L79 (25.433, -33.159) -> (42.896, -43.2346)
  line L80 (30.629, -34.173) -> (29.7699, -35.6612)
  line L81 (-30.2298, -35.6615) -> (-29.3244, -34.0923)
  line L82 (-90.23, -35.6618) -> (-75.3719, -44.2345)
  line L83 (-90.23, -35.6618) -> (-89.3244, -34.0922)
  line L84 (-90.23, -35.6618) -> (-94.567, -33.159)
  line L85 (-144.567, -33.159) -> (-124.5058, -44.7345)
  line L86 (-139.3638, -36.1613) -> (-138.4584, -34.5922)
  line L87 (-204.567, -33.159) -> (-183.6398, -45.2345)
  line L88 (-198.4977, -36.6611) -> (-197.5924, -35.0922)
  line L89 (-264.567, -33.159) -> (-242.7738, -45.7345)
  line L90 (-257.6316, -37.161) -> (-256.7263, -35.5922)
  line L91 (-326.2039, -23.3339) -> (-319.2703, -27.337)
  line L92 (-331.2993, -32.1594) -> (-346.979, -23.1067)
  line L93 (-343.0816, -25.3568) -> (-340.0816, -20.1607)
  line L94 (-299.5746, -50.467) -> (-297.0726, -49.0156)
  line L95 (-343.0816, -25.3568) -> (-340.0816, -20.1607)
  line L96 (-334.0816, -20.1607) -> (-340.0816, -20.1607)
  line L97 (-326.2039, -23.3339) -> (-341.8775, -14.2709)
  line L98 (-303.3473, -36.5287) -> (-319.2703, -27.337)
  line L99 (-331.2993, -32.1594) -> (-326.2039, -23.3339)
  line L100 (-319.2703, -27.337) -> (-323.4586, -34.5926)
  line L101 (-299.5746, -50.467) -> (-307.7738, -45.7345)
  line L102 (-331.2993, -32.1594) -> (-307.7738, -45.7345)
  line L103 (-341.8775, -14.2709) -> (-346.979, -23.1067)
  line L104 (-324.3639, -36.1614) -> (-323.4586, -34.5926)
  line L105 (-326.0961, -35.1618) -> (-324.3639, -36.1614)
  line L106 (-393.0316, -31.1598) -> (-367.7738, -45.7345)
  line L107 (-381.0025, -26.3374) -> (-385.1909, -33.593)
  line L108 (-386.0961, -35.1618) -> (-385.1909, -33.593)
  line L109 (-393.0316, -31.1598) -> (-408.7112, -22.1071)
  line L110 (-403.6098, -13.2713) -> (-408.7112, -22.1071)
  line L111 (-387.9362, -22.3343) -> (-403.6098, -13.2713)
  line L112 (-395.8139, -19.1611) -> (-401.8139, -19.1611)
  line L113 (-387.9362, -22.3343) -> (-381.0025, -26.3374)
  line L114 (-393.0316, -31.1598) -> (-387.9362, -22.3343)
  line L115 (-359.5746, -50.467) -> (-367.7738, -45.7345)
  line L116 (-404.8139, -24.3572) -> (-401.8139, -19.1611)
  line L117 (-363.3476, -36.5288) -> (-381.0025, -26.3374)
  line L118 (-404.8139, -24.3572) -> (-401.8139, -19.1611)
  line L119 (-359.5746, -50.467) -> (-357.0726, -49.0156)
  line L120 (-387.8284, -34.1622) -> (-386.0961, -35.1618)
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  point P3 (16.6506, -21.1603)
  point P13 (16.6506, -21.1603)
  point P16 (13.6506, -26.3564)
  point P22 (-43.3494, -21.1603)
  point P33 (-43.3494, -21.1603)
  point P35 (-46.3494, -26.3564)
  point P48 (-103.3494, -21.1603)
  point P55 (-103.3494, -21.1603)
  point P47 (-106.3494, -26.3564)
  point P67 (-153.3494, -21.1603)
  point P78 (-153.3494, -21.1603)
  point P65 (-156.3494, -26.3564)
  point P92 (-213.3494, -21.1603)
  point P94 (-213.3494, -21.1603)
  point P93 (-216.3494, -26.3564)
  point P111 (-273.3494, -21.1603)
  point P115 (-273.3494, -21.1603)
  point P112 (-276.3494, -26.3564)
  point P127 (29.7699, -35.6612)
  point P130 (-139.3638, -36.1613)
  point P131 (-198.4977, -36.6611)
  point P132 (-257.6316, -37.161)
  point P138 (-340.0816, -20.1607)
  point P139 (-340.0816, -20.1607)
  point P136 (-343.0816, -25.3568)
  point P133 (-324.3639, -36.1614)
  point P155 (-401.8139, -19.1611)
  point P161 (-401.8139, -19.1611)
  point P159 (-404.8139, -24.3572)
  point P158 (-386.0961, -35.1618)
  point P14 (13.6506, -26.3564)
  point P34 (-46.3494, -26.3564)
  point P30 (-11.811, -34.5286)
  point P40 (-10.945, -35.0285)
  point P28 (-16.2379, -41.6478)
  point P41 (-15.3719, -42.1478)
  point P46 (-106.3494, -26.3564)
  point P49 (-69.7504, -35.7181)
  point P61 (-70.6165, -35.2181)
  point P51 (-74.5059, -42.6477)
  point P54 (-75.3719, -42.1477)
  point P74 (-156.3494, -26.3564)
  point P72 (-119.2129, -36.0285)
  point P83 (-120.0789, -35.5285)
  point P75 (-123.6398, -43.1477)
  point P77 (-124.5059, -42.6477)
  point P98 (-216.3494, -26.3564)
  point P91 (-178.3469, -36.5285)
  point P105 (-179.2129, -36.0285)
  point P99 (-182.7738, -43.6477)
  point P101 (-183.6398, -43.1477)
  point P124 (-276.3494, -26.3564)
  point P146 (-343.0816, -25.3568)
  point P153 (-326.0961, -35.1618)
  point P167 (-404.8139, -24.3572)
  point P154 (-387.8284, -34.1622)
  perpendicular L3 L4
  perpendicular L3 L6
  perpendicular L5 L7
  horizontal L9
  coincident P3 P13
  perpendicular L4 L8
  coincident L8 P16
  coincident L4 P16
  perpendicular L15 L19
  perpendicular L13 L18
  horizontal L21
  coincident P22 P33
  coincident P35 L22
  parallel L18 L23
  perpendicular L36 L38
  perpendicular L35 L36
  perpendicular L31 L33
  horizontal L26
  coincident P48 P55
  perpendicular L28 L38
  coincident P47 L28
  coincident P47 L38
  parallel L30 L31
  perpendicular L45 L47
  perpendicular L45 L48
  perpendicular L46 L50
  horizontal L41
  coincident P67 P78
  perpendicular L39 L47
  coincident P65 L39
  coincident P65 L47
  parallel L42 L50
  perpendicular L53 L64
  perpendicular L60 L64
  perpendicular L62 L66
  horizontal L55
  coincident P92 P94
  perpendicular L53 L57
  coincident P93 L57
  coincident P93 L53
  parallel L61 L62
  perpendicular L67 L78
  perpendicular L71 L78
  perpendicular L70 L72
  horizontal L75
  coincident P111 P115
  perpendicular L67 L77
  coincident P112 L77
  coincident P112 L67
  coincident L79 P127
  parallel L7 L80
  parallel L34 L82
  perpendicular L82 L83
  coincident L85 P130
  perpendicular L85 L86
  coincident L87 P131
  perpendicular L87 L88
  coincident L89 P132
  perpendicular L89 L90
  perpendicular L92 L99
  perpendicular L91 L99
  perpendicular L98 L100
  horizontal L96
  coincident P138 P139
  perpendicular L92 L93
  coincident P136 L93
  coincident P136 L92
  coincident P133 L102
  perpendicular L102 L104
  perpendicular L104 L105
  perpendicular L109 L114
  perpendicular L113 L114
  perpendicular L107 L117
  horizontal L112
  coincident P155 P161
  perpendicular L109 L118
  coincident P159 L118
  coincident P159 L109
  coincident P158 L106
  perpendicular L106 L108
  perpendicular L108 L120
  dimension "d206" diameter = 6.5
  dimension "d232" angle L8 L9 = 120
  dimension "d233" distance P13 P14 = 6
  dimension "d237" diameter = 6.5
  dimension "d238" angle L21 L22 = 120
  dimension "d239" distance P33 P34 = 6
  dimension "d240" distance P30 P40 = 1
  dimension "d241" distance P28 P41 = 1
  dimension "d242" diameter = 6.5
  dimension "d243" angle L26 L28 = 120
  dimension "d244" distance P46 P48 = 6
  dimension "d245" distance P49 P61 = 1
  dimension "d246" distance P51 P54 = 1
  dimension "d247" diameter = 6.5
  dimension "d248" angle L39 L41 = 120
  dimension "d249" distance P67 P74 = 6
  dimension "d250" distance P72 P83 = 1
  dimension "d251" distance P75 P77 = 1
  dimension "d252" diameter = 6.5
  dimension "d253" angle L55 L57 = 120
  dimension "d254" distance P94 P98 = 6
  dimension "d255" distance P91 P105 = 1
  dimension "d256" distance P99 P101 = 1
  dimension "d257" diameter = 6.5
  dimension "d258" angle L75 L77 = 120
  dimension "d259" distance P115 P124 = 6
  dimension "d350" radius = 7
  dimension "d351" radius = 7
  dimension "d352" radius = 6.7
  dimension "d353" radius = 7
  dimension "d354" radius = 7
  dimension "d355" radius = 7
  dimension "d421" diameter = 6.5
  dimension "d422" angle L93 L96 = 120
  dimension "d423" distance P139 P146 = 6
  dimension "d424" radius = 7
  dimension "d425" distance P133 P153 = 2
  dimension "d426" diameter = 6.5
  dimension "d427" angle L112 L118 = 120
  dimension "d428" distance P155 P167 = 6
  dimension "d429" radius = 7
  dimension "d430" distance P154 P158 = 2
  dimension "d458" angle = 150
work_plane "WorkPlane6" sketch "Flipper" AlongDistance 11
sketch "Rubber Band Line" plane through (0, 0, 11) normal (0, 0, 1) x axis (1, 0, 0)
  line L1 (47.766, 7.9632) -> (0.9915, 12.4623)
  line L2 (0.1878, -12.5003) -> (47.7564, -7.9642)
  arc A1 centre (0, 0) radius 12.5017 clockwise from (0.1878, -12.5003) to (0.9915, 12.4623)
  arc A2 centre (47, 0) radius 8 clockwise from (47.766, 7.9632) to (47.7564, -7.9642)
work_plane "WorkPlane7" PathDistance 0.8475
sketch "Rubber Band profile" plane through (23.6498, 10.2829, 13) normal (0.9954, -0.0957, 0) x axis (0.0957, 0.9954, 0)
  line L1 (-2.5, 5.1) -> (-2.5, -5.1)
  line L2 (2.5, -5.1) -> (2.5, 5.1)
  line L3 (2.5, 7.1) -> (-2.5, 5.1)
  line L4 (2.5, 7.1) -> (2.5, 5.1)
  line L5 (2.5, -7.1) -> (-2.5, -5.1)
  line L6 (2.5, -5.1) -> (2.5, -7.1)
  circle C1 centre (0, 0) radius 2
  point P1 (0, 0)
  point P2 (0, 0)
  coincident P1 P2
sweep "Sweep1" sketch "Rubber Band profile" TwistAngle 0 TaperAngle 0
sketch "Silicon Chip Logo Flipper" plane through (0, 0, 25.7) normal (0, 0, 1) x axis (-1, 0, 0)
  line L1 (-47.7564, 7.9642) -> (0, 12.5)
  line L2 (-1.1968, -12.4426) -> (-47.766, -7.9632)
  curve K1
  curve K2
  curve K3
  curve K4
  line L3 (-47.7564, 7.9642) -> (0, 12.5)
  line L4 (-1.1968, -12.4426) -> (-47.766, -7.9632)
  arc A1 centre (0, 0) radius 12.5 clockwise from (0, 12.5) to (-1.1968, -12.4426)
  arc A2 centre (-47, 0) radius 8 clockwise from (-47.766, -7.9632) to (-47.7564, 7.9642)
  arc A3 centre (0, 0) radius 12.5 clockwise from (0, 12.5) to (-1.1968, -12.4426)
  arc A4 centre (-47, 0) radius 8 clockwise from (-47.766, -7.9632) to (-47.7564, 7.9642)
  dimension "d116" Text1-Height = 7
extrude "Extrude31" cut sketch "Flipper Drive Lower Assembly" profile of C2 C3 C4 C5 along normal blind 20
extrude "Extrude28" cut sketch "Silicon Chip Logo Flipper" against normal blind 0.6
sketch "37mm solenoid drill" plane through (0, 0, -46) normal (0, 0, -1) x axis (1, 0, 0)
  line L1 (-72.6464, -35.307) -> (-73.3163, -35.307)
  line L2 (-92.7503, -29.6387) -> (-60.4463, -11.5985)
  line L3 (-82.7298, -46.9948) -> (-92.7503, -29.6387)
  line L4 (-50.4258, -28.9545) -> (-82.7298, -46.9948)
  line L5 (-51.4186, -22.4904) -> (-55.4186, -15.5622)
  line L6 (-49.0676, -21.307) -> (-73.3163, -35.307)
  line L7 (-47.3633, -20.323) -> (-49.0676, -21.307)
  line L8 (-47.3633, -20.323) -> (-53.3977, -23.807)
  line L9 (-60.4463, -11.5985) -> (-53.3977, -23.807)
  line L10 (-39.3006, -23.807) -> (-53.3977, -23.807)
  line L11 (-50.4258, -28.9545) -> (-60.4463, -11.5985)
  line L12 (-92.7503, -29.6387) -> (-60.4463, -11.5985)
  line L13 (-44.7375, -18.807) -> (-49.0676, -21.307)
  circle C1 centre (-77.3163, -28.3788) radius 1.75
  circle C2 centre (-55.9958, -25.307) radius 1.75
  circle C3 centre (-59.9958, -18.3788) radius 1.75
  circle C4 centre (-73.3163, -35.307) radius 1.75
  circle C5 centre (-77.3163, -28.3788) radius 4
  circle C6 centre (-73.3163, -35.307) radius 4
  circle C7 centre (-59.9958, -18.3788) radius 4
  circle C8 centre (-55.9958, -25.307) radius 4
  point P7 (-73.3163, -35.307)
  point P12 (-73.3163, -35.307)
  point P13 (-49.0676, -21.307)
  point P17 (-60.4463, -11.5985)
  point P20 (-92.7503, -29.6387)
  point P25 (-44.7375, -18.807)
  parallel L2 L4
  coincident P7 P12
  perpendicular L5 L6
  horizontal L10
  parallel L9 L11
  parallel L2 L12
  concentric C1 C5
  concentric C4 C6
  concentric C3 C7
  concentric C2 C8
  perpendicular L5 L13
  dimension "d121" diameter C1 = 3.5
  dimension "d122" diameter C2 = 3.5
  dimension "d123" diameter C3 = 3.5
  dimension "d147" diameter C4 = 3.5
  dimension "d329" distance P12 P13 = 28
  dimension "d330" angle L9 L10 = 120
  dimension "d331" distance P17 P20 = 37
  dimension "d332" diameter C5 = 8
  dimension "d333" diameter C6 = 8
  dimension "d334" diameter C7 = 8
  dimension "d335" diameter C8 = 8
  dimension "d370" distance P13 P25 = 5
extrude "Extrude29" cut sketch "37mm solenoid drill" profile of C1 C2 C3 C4 L6 against normal blind 120
move "Move10" RotateAngle 180
sketch "22mm solenoid drill" plane through (0, 0, -45.2) normal (0, 0, -1) x axis (1, 0, 0)
  line L1 (-48.4737, -23.7852) -> (-73.4142, -23.7852)
  line L2 (-27.7707, -26.4275) -> (-53.9908, -26.4275)
  circle C1 centre (-37.5345, -16.9307) radius 1.8
  circle C2 centre (-56.9579, -14.2884) radius 1.8
  circle C3 centre (-73.4142, -23.7852) radius 1.75
  circle C4 centre (-53.9908, -26.4275) radius 1.75
  circle C5 centre (-53.9908, -26.4275) radius 4
  circle C6 centre (-73.4142, -23.7852) radius 4
  circle C7 centre (-59.9908, -16.0352) radius 1.75
  circle C8 centre (-59.9908, -16.0352) radius 4
  circle C9 centre (-67.4142, -34.1775) radius 1.75
  circle C10 centre (-67.4142, -34.1775) radius 4
  point P4 (-73.4142, -23.7852)
  point P8 (-73.4142, -23.7852)
  point P6 (-53.9908, -26.4275)
  point P10 (-53.9908, -26.4275)
  horizontal L1
  coincident P4 P8
  horizontal L2
  coincident P6 P10
  dimension "d127" diameter C3 = 3.5
  dimension "d128" diameter C4 = 3.5
  dimension "d339" diameter C5 = 8
  dimension "d340" diameter C6 = 8
  dimension "d469" diameter C7 = 3.5
  dimension "d470" diameter C8 = 8
  dimension "d471" diameter C9 = 3.5
  dimension "d472" diameter C10 = 8
work_plane "WorkPlane8" sketch "Flipper Drive Perpendicular Plane" AlongDistance 20
sketch "Drive Hole Expansion Calcs" plane through (-17.3205, 10, 0) normal (-0.866, 0.5, 0) x axis (-0.5, -0.866, 0)
  line L1 (-20, -32.2) -> (-18, -32.2)
  line L2 (0, -34.2) -> (20.0402, -34.1996)
  line L3 (20, -30.2) -> (0, -30.2)
  line L4 (0, -34.2) -> (0, -34.2)
  line L5 (0, -30.2) -> (0, -30.2)
  arc A1 centre (20, -32.2) radius 2 clockwise from (20, -30.2) to (19.9599, -34.1996)
  circle C1 centre (10, -32.2) radius 2
  arc A2 centre (0, -32.2) radius 2 clockwise from (0, -34.2) to (0, -30.2)
  point P7 (20.0402, -34.1996)
  point P12 (19.9599, -34.1996)
  point P14 (0, -30.2)
  point P15 (0, -34.2)
  coincident P7 A1
  tangent L2 A2
  tangent L3 A1
  horizontal L4
  parallel L1 L5
  coincident L2 P12
  coincident A2 P14
  coincident A2 P15
  dimension "d171" diameter A2 = 4
  dimension "d172" diameter A1 = 4
  dimension "d174" diameter C1 = 4
extrude "Extrude30" cut sketch "22mm solenoid drill" profile of C3 C4 against normal blind 50
extrude "Extrude33" add sketch "Flipper Drive Top Labelling" profile of C1 C2 along normal blind 1
extrude "Extrude34" add sketch "Flipper Drive Top Labelling" profile of C2 C3 along normal blind 7.7
sketch "Solenoid Drive Washer" plane through (0, 0, -21.4) normal (0, 0, -1) x axis (1, 0, 0)
  line L1 (-20.2309, -4.9709) -> (-24.4204, 2.2855)
  line L2 (-7.0612, 0.7412) -> (2.8887, 6.4858)
  line L3 (7.0612, -0.7412) -> (-2.8887, -6.4858)
  arc A1 centre (-5, 8.6603) radius 6 clockwise from (-10.8144, 10.1409) to (-6.625, 2.8845)
  circle C1 centre (-5, 8.6603) radius 6
  circle C2 centre (-5, 8.6603) radius 1.75
  arc A2 centre (0, 0) radius 7.1 clockwise from (2.8887, 6.4858) to (7.0612, -0.7412)
  arc A3 centre (0, 0) radius 7.1 clockwise from (-2.8887, -6.4858) to (-7.0612, 0.7412)
  circle C3 centre (0, 0) radius 15
extrude "Extrude36" new body sketch "Solenoid Drive Washer" profile of A1 C1 C2 blind 1 from offset 0.2 bodies "Drive Arm Washer"
extrude "Extrude37" cut sketch "Flipper Drive Top Labelling" profile of C3 against normal blind 6
extrude "Extrude38" new body sketch "Solenoid Coupling" along normal blind 1.5 and against normal blind 1.5 bodies "Solenoid Coupling 38mm"
extrude "Extrude39" add sketch "Solenoid Coupling" profile of L3 L6 L7 along normal blind 7.6 and against normal blind 7.5
extrude "Extrude40" add sketch "Solenoid Coupling" blind 3 from offset 4.5
extrude "Extrude41" add sketch "Solenoid Coupling" blind -3 from offset -4.5
move "Move17"
move "Move18"
move "Move19"
move_face "MoveFace2"
extrude "Extrude42" new body sketch "Solenoid Coupling" along normal blind 1.5 and against normal blind 1.5 bodies "Solenoid Coupling 41mm", "Solenoid Coupling 42mm", "Solenoid Coupling 40mm", "Solenoid Coupling 43mm", "Solenoid Coupling 39mm"
extrude "Extrude43" new body sketch "Solenoid Coupling" blind 3 from offset 4.5
extrude "Extrude44" new body sketch "Solenoid Coupling" blind -3 from offset -4.5
extrude "Extrude45" add sketch "Solenoid Coupling" profile of L13 L15 L19 L33 L35 L36 L45 L46 L48 L60 L64 L66 L71 L72 L78 along normal blind 5.5 and against normal blind 5.5
chamfer "Chamfer1" distance 2 distance 5
sketch "Coupling base labelling" plane through (0, 0, -31.4) normal (0, 0, 1) x axis (-1, 0, 0)
  dimension "d278" = 6
  dimension "d279" = "'38'"
  dimension "d280" = 6
  dimension "d281" = "'38'"
extrude "Extrude48" add sketch "Flipper Drive" profile of C1 L9 L11 L13 L14 A5 A6 blind 8.8 from offset 11.2
extrude "Extrude49" new body sketch "Flipper Drive" profile of L5 L7 L15 L17 L18 L20 L21 L23 A7 A8 A9 A10 L24 L26 A11 L28 L29 A14 A15 A16 A17 A18 A19 A20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 blind 10 from offset 10 bodies "Drive Limiter"
move "Move20"
move "Move21"
extrude "Extrude51" cut sketch "37mm solenoid drill" profile of C1 C2 C3 C4 L6 C5 C6 C7 C8 blind 8 from offset -40
extrude "Extrude52" cut sketch "22mm solenoid drill" profile of C2 C3 C4 C5 C6 C7 C8 C9 C10 blind 8 from offset -39
extrude "Extrude53" cut sketch "22mm solenoid drill" profile of C2 C3 C4 C7 C9 against normal blind 100 taper 0.1
extrude "Extrude46" cut sketch "Coupling base labelling" against normal blind 0.4
sketch "Coupling Labelling" plane through (0, 0, -30.7) normal (0, 0, 1) x axis (-1, 0, 0)
  dimension "d284" = 6
  dimension "d285" = "'39'"
  dimension "d286" = 6
  dimension "d287" = 0 (= "Text2-Text")
  dimension "d288" = 6
  dimension "d289" = "'39'"
  dimension "d290" = 6
  dimension "d291" = "'41'"
  dimension "d292" = 6
  dimension "d293" = "'42'"
  dimension "d294" = 6
  dimension "d295" = "'43'"
extrude "Extrude47" cut sketch "Coupling Labelling" against normal blind 0.4
work_plane "WorkPlane10" AlongDistance 2.7
move "Move22"
move "Move23"
extrude "Extrude54" cut sketch "Flipper" profile of C2 C3 blind -12 from offset -20
move_face "MoveFace3"
sketch "Flipper Dimensions" plane through (0, 0, 0) normal (0, 0, -1) x axis (1, 0, 0)
  dimension "d371" = 6
  dimension "d377" = 6
  dimension "d378" = "'Flipper + 1'"
  dimension "d379" = 6
  dimension "d380" = "'Flipper+0.5'"
extrude "Extrude57" cut sketch "Flipper Dimensions" against normal blind 0.4
move_face "MoveFace4"
move_face "MoveFace5"
move "Move26"
sketch "Flipper Labelling + 1" plane through (0, 0, 0.7) normal (0, 0, 1) x axis (1, 0, 0)
  curve K1
  curve K2
  curve K3
  curve K4
  line L1 (47.766, 7.9632) -> (1.1968, 12.4426)
  line L2 (0, -12.5) -> (47.7564, -7.9642)
  line L3 (47.766, 7.9632) -> (1.1968, 12.4426)
  line L4 (0, -12.5) -> (47.7564, -7.9642)
  line L5 (47.766, 7.9632) -> (1.1968, 12.4426)
  line L6 (0, -12.5) -> (47.7564, -7.9642)
  circle C1 centre (0, 0) radius 6.8
  arc A1 centre (0, 0) radius 12.5 clockwise from (0, -12.5) to (1.1968, 12.4426)
  arc A2 centre (47, 0) radius 8 clockwise from (47.766, 7.9632) to (47.7564, -7.9642)
  circle C2 centre (0, 0) radius 6.8
  arc A3 centre (0, 0) radius 12.5 clockwise from (0, -12.5) to (1.1968, 12.4426)
  arc A4 centre (47, 0) radius 8 clockwise from (47.766, 7.9632) to (47.7564, -7.9642)
  circle C3 centre (0, 0) radius 6.8
  arc A5 centre (0, 0) radius 12.5 clockwise from (0, -12.5) to (1.1968, 12.4426)
  arc A6 centre (47, 0) radius 8 clockwise from (47.766, 7.9632) to (47.7564, -7.9642)
  dimension "d397" Text1-Height = 7
  dimension "d398" Flipper+1 = "'Flipper+1'"
extrude "Extrude64" new body sketch "Bushing" blind -9.8 from offset -0.6 bodies "Bushing + 1"
sketch "Sketch35" plane through (0, 0, 0) normal (0, 1, 0) x axis (1, 0, 0)
  dimension "d412" = 3
  dimension "d413" = "'Bushing+1'"
emboss "Emboss1" sketch "Sketch35" Depth -0.4 Horizontal Distance 0 Vertical Distance 0 Rotation Angle 0
extrude "Extrude65" new body sketch "Washers Upper" blind -0.6 from offset -0.1 bodies "Washer 0.6"
extrude "Extrude66" new body sketch "Solenoid Coupling" along normal blind 1.5 and against normal blind 1.5 bodies "Solenoid Coupling 47mm", "Solenoid Coupling 45mm"
chamfer "Chamfer2" distance 2 distance 4
extrude "Extrude67" add sketch "Solenoid Coupling" profile of L91 L99 L100 L102 L104 L105 L106 L107 L108 L113 L114 L120 along normal blind 5.5 and against normal blind 5.5
extrude "Extrude68" add sketch "Solenoid Coupling" blind -3 from offset -4.5
extrude "Extrude69" add sketch "Solenoid Coupling" blind 3 from offset 4.5
chamfer "Chamfer3" distance 4 distance 2
chamfer "Chamfer4" distance 4 distance 2
sketch "Sketch36" plane through (0, 0, -33.7) normal (0, 0, -1) x axis (1, 0, 0)
  dimension "d451" = 6
  dimension "d452" = "'45'"
  dimension "d453" = 6
  dimension "d454" = "'47'"
extrude "Extrude70" cut sketch "Sketch36" against normal blind 0.4
mirror "Mirror4" mirrorStitchTolerance 0.1 bodies "Flipper Drive Mirrored"
move "Move27"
